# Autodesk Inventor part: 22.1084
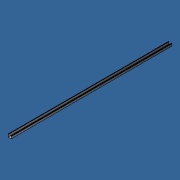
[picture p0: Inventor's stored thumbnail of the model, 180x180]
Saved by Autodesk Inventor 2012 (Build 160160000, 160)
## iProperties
Created: 2007-05
Part Number: 22.1084
Document SubType Name: Modeling
Designer: Andy Moles
Material: PVC-U
Density: 1.4 g/cm^3
Description: CONDUIT 45 BOTTOM
Stock Number: 22.1084 CONDUIT 45 BOTTOM
Author: Andy Moles
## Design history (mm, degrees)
sketch "Sketch1"
  geometry: L1 (17.5, 0)-(-17.5, 0); L2 (20.5, 26.83)-(20.5, 3); L3 (17.701, 32.75)-(19.964, 28.83); L4 (18.916, 35.76)-(19.225, 35.226); L5 (18.232, 28.83)-(16.402, 32); L6 (18.5, 3)-(18.5, 27.83); L7 (-18.5, 27.83)-(-18.5, 3); L8 (-16.402, 32)-(-18.232, 28.83); L9 (-19.225, 35.226)-(-18.916, 35.76); L10 (-19.964, 28.83)-(-17.701, 32.75); L11 (-20.5, 3)-(-20.5, 26.83); L12 (-17.5, 2)-(17.5, 2); A1 r 3 centre (17.5, 3) between (17.5, 0) and (20.5, 3); A2 r 4 centre (16.5, 26.83) between (20.5, 26.83) and (19.964, 28.83); A3 r 1.5 centre (19, 33.5) between (18.85, 34.992) and (17.701, 32.75); A4 r 0.5 centre (18.8, 35.49) between (18.85, 34.992) and (19.225, 35.226); A5 r 1 centre (18.05, 35.26) between (18.916, 35.76) and (17.575, 36.14); A6 r 3 centre (19, 33.5) between (17.575, 36.14) and (16.402, 32); A7 r 2 centre (16.5, 27.83) between (18.5, 27.83) and (18.232, 28.83); A8 r 1 centre (17.5, 3) between (17.5, 2) and (18.5, 3); A9 r 1 centre (-17.5, 3) between (-18.5, 3) and (-17.5, 2); A10 r 2 centre (-16.5, 27.83) between (-18.232, 28.83) and (-18.5, 27.83); A11 r 3 centre (-19, 33.5) between (-16.402, 32) and (-17.575, 36.14); A12 r 1 centre (-18.05, 35.26) between (-17.575, 36.14) and (-18.916, 35.76); A13 r 0.5 centre (-18.8, 35.49) between (-19.225, 35.226) and (-18.85, 34.992); A14 r 1.5 centre (-19, 33.5) between (-17.701, 32.75) and (-18.85, 34.992); A15 r 4 centre (-16.5, 26.83) between (-19.964, 28.83) and (-20.5, 26.83); A16 r 3 centre (-17.5, 3) between (-20.5, 3) and (-17.5, 0); 1 further point
  constraints: 32 point on circle, 28 tangent, 24 end point, 16 centre point, 9 equal radius, 7 parallel, 4 coincident with centre, 3 equal length, 3 horizontal alignment, 1 perpendicular, 1 vertical
  dimensions: "d71" = 3 radius of A11; "d72" = 1 radius of A12; "d73" = 0.53409 vertical distance of L9.start L9.end; "d74" = 0.5 radius of A13; "d75" = 1.5 radius of A14; "d77" = 4.52631 distance of L10.start L10.end; "d78" = 3.99991 radius of A15; "d79" = 1.99996 radius of A10; "d82" = 1 radius of A9 (derived); "d83" = 3 radius of A16 (derived); "d84" = 3 radius of A1 (derived); "d85" = 1 radius of A8 (derived); "d88" = 41 distance between parallel lines of L2 L11; "d89" = 0.74971 horizontal distance of A12.centre A13.centre; "d93" = 23.83013 vertical distance of A9.centre A15.centre; "d94" = 0.74971 horizontal distance of A5.centre A4.centre; "d99" = 35 distance of L12.start L12.end (derived)
extrude "Extrusion1" new body sketch "Sketch1" stored distance "d102" = 1999.996; taper "d103" = 0 deg
sketch "Sketch2"
  geometry: L1 (35, 1999.996)-(0, 1999.996) reference; L2 (35, 0)-(35, 1999.996) reference; L3 (19.65, 1921.846)-(19.65, 1918.446); L4 (15.35, 1921.846)-(15.35, 1918.446); L5 (20.65, 1898.646)-(20.65, 1891.446); L6 (14.35, 1898.646)-(14.35, 1891.446); A1 r 2.15 centre (17.5, 1921.846) between (19.65, 1921.846) and (15.35, 1921.846); A2 r 2.15 centre (17.5, 1918.446) between (15.35, 1918.446) and (19.65, 1918.446); A3 r 3.15 centre (17.5, 1898.646) between (20.65, 1898.646) and (14.35, 1898.646); A4 r 3.15 centre (17.5, 1891.446) between (14.35, 1891.446) and (20.65, 1891.446); 2 further points
  constraints: 8 end point, 8 point on circle, 5 tangent, 4 centre point, 4 vertical alignment, 2 equal radius, 1 midpoint, 1 parallel
  dimensions: "d105" = 4.3 distance between parallel lines of L4 L3; "d106" = 7.7 dimension on A1 A2; "d107" = 76 distance edge to line of A1 L1; "d109" = 6.3 distance between parallel lines of L6 L5; "d110" = 13.5 dimension on A4 A3; "d111" = 14.5 dimension on A3 A2
extrude "Extrusion2" cut sketch "Sketch2" distance "d112" = 1999.996; taper "d113" = 0 deg
pattern_linear "Rectangular Pattern1" dims "d116" = 200
body "Solid1"
